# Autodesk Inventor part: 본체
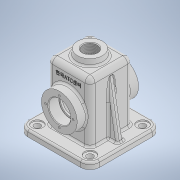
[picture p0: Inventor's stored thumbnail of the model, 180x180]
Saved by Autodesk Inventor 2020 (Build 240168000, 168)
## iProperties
Created: 2021-07
Part Number: 본체
Material: 일반
Document SubType Name: Modeling
Designer: Owner
Density: 1 g/cm^3
Appearance: 기본값
Mass: 270.432 g
Surface Area: 855.313 cm^2
Volume: 270.432 cm^3
Author: Owner
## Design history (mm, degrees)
sketch "스케치1"
  geometry: L1 (-57, 57)-(57, 57); L2 (57, 57)-(57, -57); L3 (57, -57)-(-57, -57); L4 (-57, -57)-(-57, 57); L5 (-57, 57)-(57, -57); L6 (57, 57)-(-57, -57); 1 further point
  constraints: 12 end point, 2 midpoint, 2 parallel, 1 horizontal, 1 perpendicular
  dimensions: "d0" = 114 distance of L2.end L3.end; "d1" = 114 distance of L1.end L2.end
extrude "돌출1" new body sketch "스케치1" distance "d2" = 10; taper "d3" = 0 deg
fillet "모깎기1" dims "d4" = 15
sketch "스케치2"
  geometry: A1 r 15 centre (-42, 42) between (-42, 57) and (-57, 42) reference; 2 further points
  constraints: 1 coincident
hole "구멍1" sketch "스케치2" at (-42, 42) diameter "d5" = 10; stored, may be unused: countersink angle "d9" = 90 deg, drill point angle "d11" = 0 deg; dims "d6" = 30, "d7" = 18, "d8" = 2, "d10" = 10
sketch "스케치3"
  geometry: L1 (34, -34)-(-34, -34); L2 (-34, -34)-(-34, 34); L3 (-34, 34)-(34, 34); L4 (34, 34)-(34, -34); L5 (34, -34)-(-34, 34); L6 (-34, -34)-(34, 34); 1 further point
  constraints: 12 end point, 2 midpoint, 2 parallel, 1 horizontal, 1 perpendicular
  dimensions: "d12" = 68 distance of L2.end L3.end; "d13" = 68 distance of L1.end L2.end
extrude "돌출2" join sketch "스케치3" distance "d14" = 95; taper "d15" = 0 deg
sketch "스케치4"
  geometry: L1 (29, 29)-(-29, 29); L2 (-29, 29)-(-29, -29); L3 (-29, -29)-(29, -29); L4 (29, -29)-(29, 29); L5 (29, 29)-(-29, -29); L6 (-29, 29)-(29, -29); 1 further point
  constraints: 12 end point, 2 midpoint, 2 parallel, 1 horizontal, 1 perpendicular
  dimensions: "d16" = 58 distance of L1.end L2.end; "d17" = 58 distance of L2.end L3.end
extrude "돌출3" cut sketch "스케치4" distance "d18" = 100; taper "d19" = 0 deg
sketch "스케치5"
  geometry: L1 (-8, -10)-(76, -10) reference; L2 (0, 0)-(0, 95) reference; C1 r 28.5 at (34, 42); 1 further point
  constraints: 1 centre point
  dimensions: "d20" = 57 diameter of C1; "d21" = 52 distance from line of L1 C1.centre; "d22" = 34 distance from line of L2 C1.centre
extrude "돌출4" join sketch "스케치5" distance "d23" = 15; taper "d24" = 0 deg
sketch "스케치6"
  geometry: C1 r 28.5 at (0, 0) reference; 2 further points
  constraints: 1 coincident
hole "구멍2" sketch "스케치6" at (0, 0) diameter "d25" = 35; stored, may be unused: countersink angle "d29" = 90 deg, drill point angle "d31" = 0 deg; dims "d26" = 30, "d27" = 18, "d28" = 2, "d30" = 17
sketch "스케치7"
  geometry: C1 r 17.5 at (0, 0) reference; 2 further points
  constraints: 1 coincident
hole "구멍3" sketch "스케치7" at (0, 0) diameter "d32" = 30; stored, may be unused: countersink angle "d36" = 90 deg, drill point angle "d38" = 0 deg; dims "d33" = 30, "d34" = 18, "d35" = 2, "d37" = 3
fillet "모깎기2" dims "d39" = 8
node "작업 평면1"
sketch "스케치8"
  geometry: C1 r 20 at (0, 0); 1 further point
  constraints: 1 centre point, 1 coincident
  dimensions: "d41" = 40 diameter of C1
extrude "돌출5" join sketch "스케치8" stored distance "d42" = 15; taper "d43" = 8 deg
sketch "스케치9"
  geometry: C1 r 20 at (0, 0) reference; 2 further points
  constraints: 1 coincident
hole "구멍4" sketch "스케치9" at (0, 0) diameter "d44" = 22.83494; stored, may be unused: countersink angle "d48" = 82 deg, drill point angle "d50" = 0 deg; dims "d45" = 50, "d46" = 3.023, "d47" = 2, "d49" = 59.3
sketch "스케치10"
  geometry: L1 (-35.139, 88.612)-(-49, 10); L2 (-57, 10)-(-42, 10) reference; L3 (-57, 0)-(-57, 10) reference; 1 further point
  constraints: 2 end point, 1 point on line
  dimensions: "d51" = 10 deg angle of L3 L1; "d52" = 8 distance of L1.end L2.start
feature "리브1" sketch "스케치10" dims "d53" = 1, "d54" = 10, "d55" = 0, "d56" = 0, "d57" = 1, "d58" = 1
sketch "스케치11"
  geometry: L1 (-34, 45)-(-34, -42) reference; C1 r 28.5 at (0, 0) reference; 2 further points
  dimensions: "d59" = 22 distance of C1.centre point (0, 22); "d60" = 34 distance from line of L1 point (0, 22)
hole "구멍5" sketch "스케치11" at (0, 22) diameter "d61" = 3.242; stored, may be unused: countersink angle "d65" = 82 deg, drill point angle "d67" = 0 deg; dims "d62" = 8, "d63" = 3.023, "d64" = 2, "d66" = 10
sketch "스케치12"
  geometry: L1 (20, 63)-(-20, 63) reference; L2 (-34, 45)-(-34, -42) reference; 2 further points
  constraints: 1 other
  dimensions: "d71" = 25 distance from line of L1 point (0, 38); "d72" = 34 distance from line of L2 point (0, 38)
feature "엠보싱1" sketch "스케치12" dims "d73" = 0.5, "d74" = 0
chamfer "모따기1" distance "d75" = 1; stored, may be unused: second distance "d76" = 2, angle "d77" = 45 deg
fillet "모깎기3" dims "d78" = 3
fillet "모깎기4" dims "d79" = 3
fillet "모깎기5" dims "d80" = 3
fillet "모깎기6" dims "d81" = 3
fillet "모깎기7" dims "d82" = 3
fillet "모깎기8" dims "d83" = 0.3
node "솔리드1"
mirror "미러1"
mirror "미러2"
mirror "미러3"
mirror "미러4"
mirror "미러5"
mirror "미러6"
pattern_circular "원형 패턴1" dims angle "d69" = 360 deg
mirror "미러7"
feature "A9D066F2-1C7D-4E18-AEED-F7BC21143FA4" dims "d5" = 10, "d6" = 30, "d7" = 18, "d8" = 2, "d9" = 90 deg, "d10" = 10, "d11" = 0
